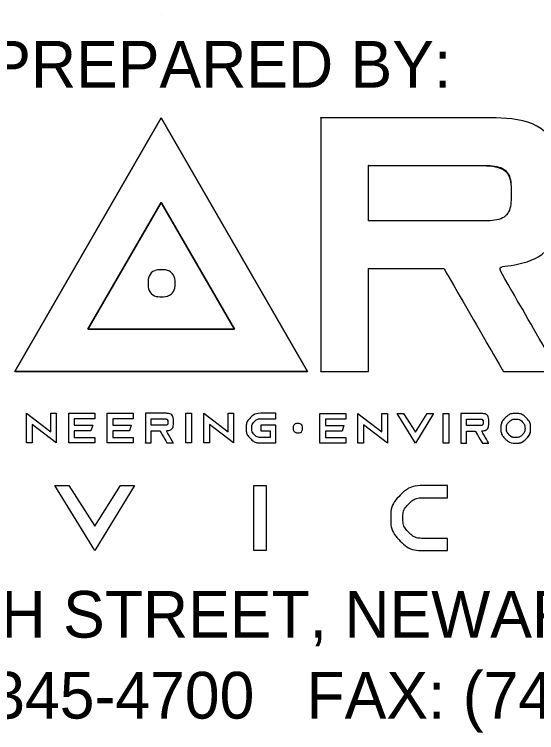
# Model space of a CAD drawing. Extents: x -50 to 112, y -27 to 22.
# Drawn here: x 110.595 to 111.147, y 2.741 to 3.5 of the extents above; entities that cross this region are included whole.
import ezdxf

# ---------------------------------------------------------------- set-up
doc = ezdxf.new("R2010")
doc.units = 0
doc.layers.add('Default', color=7, linetype='Continuous')
doc.layers.add('SH_Data', color=7, linetype='Continuous')

msp = doc.modelspace()

# ---------------------------------------------------------------- linework, layer by layer
at = {"layer": 'Default'}
for p, q in [((110.60783, 3.04681), (110.60783, 3.0782)), ((110.60783, 3.0782), (110.63334, 3.05874)), ((110.63334, 3.05874), (110.63334, 3.0782)), ((110.63334, 3.0782), (110.63922, 3.0782)), ((110.63922, 3.0782), (110.63922, 3.04681)), ((110.65238, 3.04681), (110.65238, 3.0782)), ((110.65238, 3.0782), (110.67985, 3.0782)), ((110.67985, 3.0782), (110.67985, 3.07231)), ((110.69301, 3.04681), (110.69301, 3.0782)), ((110.69301, 3.0782), (110.72047, 3.0782)), ((110.72047, 3.0782), (110.72047, 3.07231)), ((110.77623, 3.04681), (110.77623, 3.0782)), ((110.77623, 3.0782), (110.78211, 3.0782)), ((110.78211, 3.0782), (110.78211, 3.04681)), ((110.79527, 3.04681), (110.79527, 3.0782)), ((110.79527, 3.0782), (110.82078, 3.05874)), ((110.82078, 3.05874), (110.82078, 3.0782)), ((110.82078, 3.0782), (110.82666, 3.0782)), ((110.82666, 3.0782), (110.82666, 3.04681)), ((110.91766, 3.04658), (110.91766, 3.07796)), ((110.91766, 3.07796), (110.94513, 3.07796)), ((110.94513, 3.07796), (110.94513, 3.07208)), ((110.95789, 3.04658), (110.95789, 3.07796)), ((110.95789, 3.07796), (110.98339, 3.0585)), ((110.98339, 3.0585), (110.98339, 3.07796)), ((110.98339, 3.07796), (110.98928, 3.07796)), ((110.98928, 3.07796), (110.98928, 3.04658)), ((111.01871, 3.04658), (110.99947, 3.07796)), ((110.99947, 3.07796), (111.00626, 3.07796)), ((111.00626, 3.07796), (111.01871, 3.05835)), ((111.01871, 3.05835), (111.03117, 3.07796)), ((111.03796, 3.07796), (111.01871, 3.04658)), ((111.03117, 3.07796), (111.03796, 3.07796)), ((111.04815, 3.04658), (111.04815, 3.07796)), ((111.04815, 3.07796), (111.05404, 3.07796)), ((111.05404, 3.07796), (111.05404, 3.04658)), ((110.67985, 3.07231), (110.65827, 3.07231)), ((110.65827, 3.07231), (110.65827, 3.06545)), ((110.72047, 3.07231), (110.6989, 3.07231)), ((110.6989, 3.07231), (110.6989, 3.06545)), ((110.94513, 3.07208), (110.92355, 3.07208)), ((110.92355, 3.07208), (110.92355, 3.06521)), ((110.61372, 3.06627), (110.61372, 3.04681)), ((110.63922, 3.04681), (110.61372, 3.06627)), ((110.65827, 3.06545), (110.67789, 3.06545)), ((110.67789, 3.06545), (110.67592, 3.05956)), ((110.6989, 3.06545), (110.71851, 3.06545)), ((110.71851, 3.06545), (110.71655, 3.05956)), ((110.80116, 3.06627), (110.80116, 3.04681)), ((110.82666, 3.04681), (110.80116, 3.06627)), ((110.92355, 3.06521), (110.94317, 3.06521)), ((110.94317, 3.06521), (110.94121, 3.05933)), ((110.96378, 3.06604), (110.96378, 3.04658)), ((110.98928, 3.04658), (110.96378, 3.06604)), ((110.67592, 3.05956), (110.65827, 3.05956)), ((110.65827, 3.05956), (110.65827, 3.0527)), ((110.71655, 3.05956), (110.6989, 3.05956)), ((110.6989, 3.05956), (110.6989, 3.0527)), ((110.94121, 3.05933), (110.92355, 3.05933)), ((110.92355, 3.05933), (110.92355, 3.05246)), ((110.61372, 3.04681), (110.60783, 3.04681)), ((110.67985, 3.04681), (110.65238, 3.04681)), ((110.65827, 3.0527), (110.67985, 3.0527)), ((110.67985, 3.0527), (110.67985, 3.04681)), ((110.72047, 3.04681), (110.69301, 3.04681)), ((110.6989, 3.0527), (110.72047, 3.0527)), ((110.72047, 3.0527), (110.72047, 3.04681)), ((110.78211, 3.04681), (110.77623, 3.04681)), ((110.80116, 3.04681), (110.79527, 3.04681)), ((110.94513, 3.04658), (110.91766, 3.04658)), ((110.92355, 3.05246), (110.94513, 3.05246)), ((110.94513, 3.05246), (110.94513, 3.04658)), ((110.96378, 3.04658), (110.95789, 3.04658)), ((111.05404, 3.04658), (111.04815, 3.04658)), ((110.67986, 2.93307), (110.63775, 3.00176)), ((110.63775, 3.00176), (110.6526, 3.00176)), ((110.6526, 3.00176), (110.67986, 2.95883)), ((110.67986, 2.95883), (110.70713, 3.00176)), ((110.72198, 3.00176), (110.67986, 2.93307)), ((110.70713, 3.00176), (110.72198, 3.00176)), ((110.84804, 2.93307), (110.84804, 3.00176)), ((110.84804, 3.00176), (110.86092, 3.00176)), ((110.86092, 3.00176), (110.86092, 2.93307)), ((110.86092, 2.93307), (110.84804, 2.93307))]:
    msp.add_line(p, q, dxfattribs=at)
for points in [[(110.90469, 3.12236), (110.75, 3.39051), (110.59531, 3.12236)], [(110.75, 3.30103), (110.82742, 3.16703), (110.67258, 3.16703)]]:
    msp.add_lwpolyline(points, close=True, dxfattribs=at)
for points in [[(110.59531, 3.12236), (110.75, 3.39051), (110.90469, 3.12236), (110.59531, 3.12236)], [(110.67258, 3.16703), (110.82742, 3.16703), (110.75, 3.30103), (110.67258, 3.16703)], [(110.61372, 3.06627), (110.61372, 3.04681), (110.60783, 3.04681), (110.60783, 3.0782), (110.63334, 3.05874), (110.63334, 3.0782), (110.63922, 3.0782), (110.63922, 3.04681), (110.61372, 3.06627)], [(110.65827, 3.0527), (110.67985, 3.0527), (110.67985, 3.04681), (110.65238, 3.04681), (110.65238, 3.0782), (110.67985, 3.0782), (110.67985, 3.07231), (110.65827, 3.07231), (110.65827, 3.06545), (110.67789, 3.06545), (110.67592, 3.05956), (110.65827, 3.05956), (110.65827, 3.0527)], [(110.6989, 3.0527), (110.72047, 3.0527), (110.72047, 3.04681), (110.69301, 3.04681), (110.69301, 3.0782), (110.72047, 3.0782), (110.72047, 3.07231), (110.6989, 3.07231), (110.6989, 3.06545), (110.71851, 3.06545), (110.71655, 3.05956), (110.6989, 3.05956), (110.6989, 3.0527)], [(110.78211, 3.04681), (110.77623, 3.04681), (110.77623, 3.0782), (110.78211, 3.0782), (110.78211, 3.04681)], [(110.80116, 3.06627), (110.80116, 3.04681), (110.79527, 3.04681), (110.79527, 3.0782), (110.82078, 3.05874), (110.82078, 3.0782), (110.82666, 3.0782), (110.82666, 3.04681), (110.80116, 3.06627)], [(110.92355, 3.05246), (110.94513, 3.05246), (110.94513, 3.04658), (110.91766, 3.04658), (110.91766, 3.07796), (110.94513, 3.07796), (110.94513, 3.07208), (110.92355, 3.07208), (110.92355, 3.06521), (110.94317, 3.06521), (110.94121, 3.05933), (110.92355, 3.05933), (110.92355, 3.05246)], [(110.96378, 3.06604), (110.96378, 3.04658), (110.95789, 3.04658), (110.95789, 3.07796), (110.98339, 3.0585), (110.98339, 3.07796), (110.98928, 3.07796), (110.98928, 3.04658), (110.96378, 3.06604)], [(111.00626, 3.07796), (111.01871, 3.05835), (111.03117, 3.07796), (111.03796, 3.07796), (111.01871, 3.04658), (110.99947, 3.07796), (111.00626, 3.07796)], [(111.05404, 3.04658), (111.04815, 3.04658), (111.04815, 3.07796), (111.05404, 3.07796), (111.05404, 3.04658)], [(110.6526, 3.00176), (110.67986, 2.95883), (110.70713, 3.00176), (110.72198, 3.00176), (110.67986, 2.93307), (110.63775, 3.00176), (110.6526, 3.00176)], [(110.86092, 2.93307), (110.84804, 2.93307), (110.84804, 3.00176), (110.86092, 3.00176), (110.86092, 2.93307)]]:
    msp.add_lwpolyline(points, dxfattribs=at)
for points, degree in [([(110.91873, 3.39051), (110.91873, 3.39051), (110.91873, 3.12236), (110.91873, 3.12236)], 2), ([(110.91873, 3.12236), (110.91873, 3.12236), (110.96901, 3.12236), (110.96901, 3.12236), (110.96901, 3.12236), (110.96901, 3.2313), (110.96901, 3.2313), (110.96901, 3.2313), (111.04878, 3.2313), (111.04878, 3.2313), (111.04878, 3.2313), (111.11163, 3.12236), (111.11163, 3.12236), (111.11163, 3.12236), (111.16978, 3.12236), (111.16978, 3.12236), (111.16978, 3.12236), (111.1061, 3.23264), (111.1061, 3.23264), (111.14878, 3.23845), (111.17012, 3.26453), (111.17012, 3.3109), (111.17012, 3.36397), (111.14219, 3.39051), (111.08632, 3.39051), (111.08632, 3.39051), (110.91873, 3.39051), (110.91873, 3.39051)], 3), ([(110.91873, 3.39051), (110.91873, 3.39051), (111.08632, 3.39051), (111.08632, 3.39051), (111.14219, 3.39051), (111.17012, 3.36397), (111.17012, 3.3109), (111.17012, 3.26453), (111.14878, 3.23845), (111.1061, 3.23264), (111.1061, 3.23264), (111.16978, 3.12236), (111.16978, 3.12236), (111.16978, 3.12236), (111.11163, 3.12236), (111.11163, 3.12236), (111.11163, 3.12236), (111.04878, 3.2313), (111.04878, 3.2313), (111.04878, 3.2313), (110.96901, 3.2313), (110.96901, 3.2313), (110.96901, 3.2313), (110.96901, 3.12236), (110.96901, 3.12236), (110.96901, 3.12236), (110.91873, 3.12236), (110.91873, 3.12236), (110.91873, 3.12236), (110.91873, 3.39051), (110.91873, 3.39051)], 3), ([(110.96901, 3.34023), (110.96901, 3.34023), (111.08632, 3.34023), (111.08632, 3.34023)], 2), ([(111.08632, 3.34023), (111.10867, 3.34023), (111.11984, 3.33045), (111.11984, 3.3109), (111.11984, 3.29135), (111.10867, 3.28157), (111.08632, 3.28157), (111.08632, 3.28157), (110.96901, 3.28157), (110.96901, 3.28157), (110.96901, 3.28157), (110.96901, 3.34023), (110.96901, 3.34023)], 3), ([(110.96901, 3.34023), (110.96901, 3.34023), (110.96901, 3.28157), (110.96901, 3.28157), (110.96901, 3.28157), (111.08632, 3.28157), (111.08632, 3.28157), (111.10867, 3.28157), (111.11984, 3.29135), (111.11984, 3.3109), (111.11984, 3.33045), (111.10867, 3.34023), (111.08632, 3.34023), (111.08632, 3.34023), (110.96901, 3.34023), (110.96901, 3.34023)], 3), ([(110.7649, 3.21568), (110.7649, 3.20778), (110.75849, 3.20137), (110.75059, 3.20137), (110.74269, 3.20137), (110.73628, 3.20778), (110.73628, 3.21568), (110.73628, 3.22358), (110.74269, 3.22999), (110.75059, 3.22999), (110.75849, 3.22999), (110.7649, 3.22358), (110.7649, 3.21568)], 3), ([(110.7649, 3.21568), (110.7649, 3.20778), (110.75849, 3.20137), (110.75059, 3.20137), (110.74269, 3.20137), (110.73628, 3.20778), (110.73628, 3.21568), (110.73628, 3.22358), (110.74269, 3.22999), (110.75059, 3.22999), (110.75849, 3.22999), (110.7649, 3.22358), (110.7649, 3.21568)], 3), ([(110.73364, 3.0782), (110.73364, 3.0782), (110.73364, 3.04681), (110.73364, 3.04681)], 2), ([(110.73364, 3.0782), (110.73364, 3.0782), (110.75325, 3.0782), (110.75325, 3.0782), (110.75979, 3.0782), (110.76306, 3.07509), (110.76306, 3.06888), (110.76306, 3.06345), (110.76057, 3.0604), (110.75557, 3.05972), (110.75557, 3.05972), (110.76302, 3.04681), (110.76302, 3.04681), (110.76302, 3.04681), (110.75622, 3.04681), (110.75622, 3.04681), (110.75622, 3.04681), (110.74886, 3.05956), (110.74886, 3.05956), (110.74886, 3.05956), (110.73952, 3.05956), (110.73952, 3.05956), (110.73952, 3.05956), (110.73952, 3.04681), (110.73952, 3.04681), (110.73952, 3.04681), (110.73364, 3.04681), (110.73364, 3.04681), (110.73364, 3.04681), (110.73364, 3.0782), (110.73364, 3.0782)], 3), ([(110.73364, 3.04681), (110.73364, 3.04681), (110.73952, 3.04681), (110.73952, 3.04681), (110.73952, 3.04681), (110.73952, 3.05956), (110.73952, 3.05956), (110.73952, 3.05956), (110.74886, 3.05956), (110.74886, 3.05956), (110.74886, 3.05956), (110.75622, 3.04681), (110.75622, 3.04681), (110.75622, 3.04681), (110.76302, 3.04681), (110.76302, 3.04681), (110.76302, 3.04681), (110.75557, 3.05972), (110.75557, 3.05972), (110.76057, 3.0604), (110.76306, 3.06345), (110.76306, 3.06888), (110.76306, 3.07509), (110.75979, 3.0782), (110.75325, 3.0782), (110.75325, 3.0782), (110.73364, 3.0782), (110.73364, 3.0782)], 3), ([(110.85552, 3.0782), (110.85552, 3.0782), (110.87121, 3.0782), (110.87121, 3.0782), (110.87121, 3.0782), (110.87121, 3.07231), (110.87121, 3.07231), (110.87121, 3.07231), (110.85552, 3.07231), (110.85552, 3.07231), (110.85281, 3.07231), (110.8505, 3.07135), (110.84858, 3.06944), (110.84667, 3.06752), (110.84571, 3.06521), (110.84571, 3.0625), (110.84571, 3.0598), (110.84667, 3.05749), (110.84858, 3.05557), (110.8505, 3.05365), (110.85281, 3.0527), (110.85552, 3.0527), (110.85552, 3.0527), (110.86533, 3.0527), (110.86533, 3.0527), (110.86533, 3.0527), (110.86533, 3.05956), (110.86533, 3.05956), (110.86533, 3.05956), (110.85552, 3.05956), (110.85552, 3.05956), (110.85552, 3.05956), (110.85552, 3.06545), (110.85552, 3.06545), (110.85552, 3.06545), (110.87121, 3.06545), (110.87121, 3.06545), (110.87121, 3.06545), (110.87121, 3.04681), (110.87121, 3.04681), (110.87121, 3.04681), (110.85552, 3.04681), (110.85552, 3.04681), (110.85119, 3.04681), (110.84749, 3.04834), (110.84443, 3.05141), (110.84136, 3.05448), (110.83983, 3.05818), (110.83983, 3.0625), (110.83983, 3.06683), (110.84136, 3.07053), (110.84443, 3.0736), (110.84749, 3.07666), (110.85119, 3.0782), (110.85552, 3.0782)], 3), ([(110.85552, 3.0782), (110.85552, 3.0782), (110.87121, 3.0782), (110.87121, 3.0782), (110.87121, 3.0782), (110.87121, 3.07231), (110.87121, 3.07231), (110.87121, 3.07231), (110.85552, 3.07231), (110.85552, 3.07231), (110.85281, 3.07231), (110.8505, 3.07135), (110.84858, 3.06944), (110.84667, 3.06752), (110.84571, 3.06521), (110.84571, 3.0625), (110.84571, 3.0598), (110.84667, 3.05749), (110.84858, 3.05557), (110.8505, 3.05365), (110.85281, 3.0527), (110.85552, 3.0527), (110.85552, 3.0527), (110.86533, 3.0527), (110.86533, 3.0527), (110.86533, 3.0527), (110.86533, 3.05956), (110.86533, 3.05956), (110.86533, 3.05956), (110.85552, 3.05956), (110.85552, 3.05956), (110.85552, 3.05956), (110.85552, 3.06545), (110.85552, 3.06545), (110.85552, 3.06545), (110.87121, 3.06545), (110.87121, 3.06545), (110.87121, 3.06545), (110.87121, 3.04681), (110.87121, 3.04681), (110.87121, 3.04681), (110.85552, 3.04681), (110.85552, 3.04681), (110.85119, 3.04681), (110.84749, 3.04834), (110.84443, 3.05141), (110.84136, 3.05448), (110.83983, 3.05818), (110.83983, 3.0625), (110.83983, 3.06683), (110.84136, 3.07053), (110.84443, 3.0736), (110.84749, 3.07666), (110.85119, 3.0782), (110.85552, 3.0782)], 3), ([(111.0668, 3.07796), (111.0668, 3.07796), (111.0668, 3.04658), (111.0668, 3.04658)], 2), ([(111.0668, 3.07796), (111.0668, 3.07796), (111.08641, 3.07796), (111.08641, 3.07796), (111.09295, 3.07796), (111.09622, 3.07486), (111.09622, 3.06864), (111.09622, 3.06322), (111.09373, 3.06016), (111.08873, 3.05948), (111.08873, 3.05948), (111.09618, 3.04658), (111.09618, 3.04658), (111.09618, 3.04658), (111.08938, 3.04658), (111.08938, 3.04658), (111.08938, 3.04658), (111.08202, 3.05933), (111.08202, 3.05933), (111.08202, 3.05933), (111.07268, 3.05933), (111.07268, 3.05933), (111.07268, 3.05933), (111.07268, 3.04658), (111.07268, 3.04658), (111.07268, 3.04658), (111.0668, 3.04658), (111.0668, 3.04658), (111.0668, 3.04658), (111.0668, 3.07796), (111.0668, 3.07796)], 3), ([(111.0668, 3.04658), (111.0668, 3.04658), (111.07268, 3.04658), (111.07268, 3.04658), (111.07268, 3.04658), (111.07268, 3.05933), (111.07268, 3.05933), (111.07268, 3.05933), (111.08202, 3.05933), (111.08202, 3.05933), (111.08202, 3.05933), (111.08938, 3.04658), (111.08938, 3.04658), (111.08938, 3.04658), (111.09618, 3.04658), (111.09618, 3.04658), (111.09618, 3.04658), (111.08873, 3.05948), (111.08873, 3.05948), (111.09373, 3.06016), (111.09622, 3.06322), (111.09622, 3.06864), (111.09622, 3.07486), (111.09295, 3.07796), (111.08641, 3.07796), (111.08641, 3.07796), (111.0668, 3.07796), (111.0668, 3.07796)], 3), ([(111.12468, 3.04658), (111.12035, 3.04658), (111.11665, 3.04811), (111.11358, 3.05118), (111.11052, 3.05424), (111.10898, 3.05794), (111.10898, 3.06227), (111.10898, 3.0666), (111.11052, 3.0703), (111.11358, 3.07336), (111.11665, 3.07643), (111.12035, 3.07796), (111.12468, 3.07796), (111.12901, 3.07796), (111.1327, 3.07643), (111.13577, 3.07336), (111.13884, 3.0703), (111.14037, 3.0666), (111.14037, 3.06227), (111.14037, 3.05794), (111.13884, 3.05424), (111.13577, 3.05118), (111.1327, 3.04811), (111.12901, 3.04658), (111.12468, 3.04658)], 3), ([(111.13577, 3.05118), (111.13884, 3.05424), (111.14037, 3.05794), (111.14037, 3.06227), (111.14037, 3.0666), (111.13884, 3.0703), (111.13577, 3.07336), (111.1327, 3.07643), (111.12901, 3.07796), (111.12468, 3.07796), (111.12035, 3.07796), (111.11665, 3.07643), (111.11358, 3.07336), (111.11052, 3.0703), (111.10898, 3.0666), (111.10898, 3.06227), (111.10898, 3.05794), (111.11052, 3.05424), (111.11358, 3.05118), (111.11665, 3.04811), (111.12035, 3.04658), (111.12468, 3.04658)], 3), ([(110.73952, 3.07231), (110.73952, 3.07231), (110.75325, 3.07231), (110.75325, 3.07231)], 2), ([(110.73952, 3.07231), (110.73952, 3.07231), (110.73952, 3.06545), (110.73952, 3.06545), (110.73952, 3.06545), (110.75325, 3.06545), (110.75325, 3.06545), (110.75587, 3.06545), (110.75718, 3.06659), (110.75718, 3.06888), (110.75718, 3.07117), (110.75587, 3.07231), (110.75325, 3.07231), (110.75325, 3.07231), (110.73952, 3.07231), (110.73952, 3.07231)], 3), ([(110.75325, 3.07231), (110.75587, 3.07231), (110.75718, 3.07117), (110.75718, 3.06888), (110.75718, 3.06659), (110.75587, 3.06545), (110.75325, 3.06545), (110.75325, 3.06545), (110.73952, 3.06545), (110.73952, 3.06545), (110.73952, 3.06545), (110.73952, 3.07231), (110.73952, 3.07231)], 3), ([(111.07268, 3.07208), (111.07268, 3.07208), (111.08641, 3.07208), (111.08641, 3.07208)], 2), ([(111.07268, 3.07208), (111.07268, 3.07208), (111.07268, 3.06521), (111.07268, 3.06521), (111.07268, 3.06521), (111.08641, 3.06521), (111.08641, 3.06521), (111.08903, 3.06521), (111.09034, 3.06636), (111.09034, 3.06864), (111.09034, 3.07093), (111.08903, 3.07208), (111.08641, 3.07208), (111.08641, 3.07208), (111.07268, 3.07208), (111.07268, 3.07208)], 3), ([(111.08641, 3.07208), (111.08903, 3.07208), (111.09034, 3.07093), (111.09034, 3.06864), (111.09034, 3.06636), (111.08903, 3.06521), (111.08641, 3.06521), (111.08641, 3.06521), (111.07268, 3.06521), (111.07268, 3.06521), (111.07268, 3.06521), (111.07268, 3.07208), (111.07268, 3.07208)], 3), ([(111.12468, 3.05246), (111.12739, 3.05246), (111.1297, 3.05342), (111.13161, 3.05533), (111.13353, 3.05725), (111.13449, 3.05956), (111.13449, 3.06227), (111.13449, 3.06498), (111.13353, 3.06729), (111.13161, 3.0692), (111.1297, 3.07112), (111.12739, 3.07208), (111.12468, 3.07208), (111.12197, 3.07208), (111.11966, 3.07112), (111.11774, 3.0692), (111.11583, 3.06729), (111.11487, 3.06498), (111.11487, 3.06227), (111.11487, 3.05956), (111.11583, 3.05725), (111.11774, 3.05533), (111.11966, 3.05342), (111.12197, 3.05246), (111.12468, 3.05246)], 3), ([(111.11774, 3.05533), (111.11583, 3.05725), (111.11487, 3.05956), (111.11487, 3.06227), (111.11487, 3.06498), (111.11583, 3.06729), (111.11774, 3.0692), (111.11966, 3.07112), (111.12197, 3.07208), (111.12468, 3.07208), (111.12739, 3.07208), (111.1297, 3.07112), (111.13161, 3.0692), (111.13353, 3.06729), (111.13449, 3.06498), (111.13449, 3.06227), (111.13449, 3.05956), (111.13353, 3.05725), (111.13161, 3.05533), (111.1297, 3.05342), (111.12739, 3.05246), (111.12468, 3.05246)], 3), ([(110.8895, 3.06248), (110.88945, 3.06527), (110.89171, 3.06744), (110.89444, 3.06744), (110.89717, 3.06744), (110.89938, 3.06527), (110.89938, 3.06253), (110.89938, 3.05974), (110.89721, 3.05757), (110.89444, 3.05757), (110.89171, 3.05757), (110.8895, 3.05969), (110.8895, 3.06248)], 3), ([(110.8895, 3.06248), (110.88945, 3.06527), (110.89171, 3.06744), (110.89444, 3.06744), (110.89717, 3.06744), (110.89938, 3.06527), (110.89938, 3.06253), (110.89938, 3.05974), (110.89721, 3.05757), (110.89444, 3.05757), (110.89171, 3.05757), (110.8895, 3.05969), (110.8895, 3.06248)], 3), ([(111.12468, 3.05246), (111.12197, 3.05246), (111.11966, 3.05342), (111.11774, 3.05533)], 2), ([(111.12468, 3.04658), (111.12901, 3.04658), (111.1327, 3.04811), (111.13577, 3.05118)], 2), ([(111.02695, 3.00176), (111.02695, 3.00176), (111.05271, 3.00176), (111.05271, 3.00176), (111.05271, 3.00176), (111.05271, 2.98888), (111.05271, 2.98888), (111.05271, 2.98888), (111.02695, 2.98888), (111.02695, 2.98888), (111.02103, 2.98888), (111.01597, 2.98678), (111.01178, 2.98259), (111.00758, 2.9784), (111.00549, 2.97334), (111.00549, 2.96741), (111.00549, 2.96149), (111.00758, 2.95643), (111.01178, 2.95224), (111.01597, 2.94804), (111.02103, 2.94595), (111.02695, 2.94595), (111.02695, 2.94595), (111.05271, 2.94595), (111.05271, 2.94595), (111.05271, 2.94595), (111.05271, 2.93307), (111.05271, 2.93307), (111.05271, 2.93307), (111.02695, 2.93307), (111.02695, 2.93307), (111.01748, 2.93307), (111.00939, 2.93642), (111.00267, 2.94313), (110.99596, 2.94985), (110.99261, 2.95794), (110.99261, 2.96741), (110.99261, 2.97689), (110.99596, 2.98498), (111.00267, 2.99169), (111.00939, 2.9984), (111.01748, 3.00176), (111.02695, 3.00176)], 3), ([(111.02695, 3.00176), (111.02695, 3.00176), (111.05271, 3.00176), (111.05271, 3.00176), (111.05271, 3.00176), (111.05271, 2.98888), (111.05271, 2.98888), (111.05271, 2.98888), (111.02695, 2.98888), (111.02695, 2.98888), (111.02103, 2.98888), (111.01597, 2.98678), (111.01178, 2.98259), (111.00758, 2.9784), (111.00549, 2.97334), (111.00549, 2.96741), (111.00549, 2.96149), (111.00758, 2.95643), (111.01178, 2.95224), (111.01597, 2.94804), (111.02103, 2.94595), (111.02695, 2.94595), (111.02695, 2.94595), (111.05271, 2.94595), (111.05271, 2.94595), (111.05271, 2.94595), (111.05271, 2.93307), (111.05271, 2.93307), (111.05271, 2.93307), (111.02695, 2.93307), (111.02695, 2.93307), (111.01748, 2.93307), (111.00939, 2.93642), (111.00267, 2.94313), (110.99596, 2.94985), (110.99261, 2.95794), (110.99261, 2.96741), (110.99261, 2.97689), (110.99596, 2.98498), (111.00267, 2.99169), (111.00939, 2.9984), (111.01748, 3.00176), (111.02695, 3.00176)], 3)]:
    msp.add_open_spline(points, degree=degree, dxfattribs=at)
at = {"layer": 'SH_Data'}
msp.add_line((110.75, 3.5), (110.75, 3.5), dxfattribs=at)

# ---------------------------------------------------------------- texts
at = {"layer": 'Default'}
for s, p in [('PREPARED BY:', (110.56849, 3.42255)), ('88 W. CHURCH STREET, NEWARK, OHIO 43055', (110.1511, 2.84096)), ('PHONE: (740) 345-4700   FAX: (740) 522-4706', (110.12537, 2.75537))]:
    msp.add_text(s, height=0.0493871, dxfattribs=at).set_placement(p)

doc.saveas('drawing.dxf')
